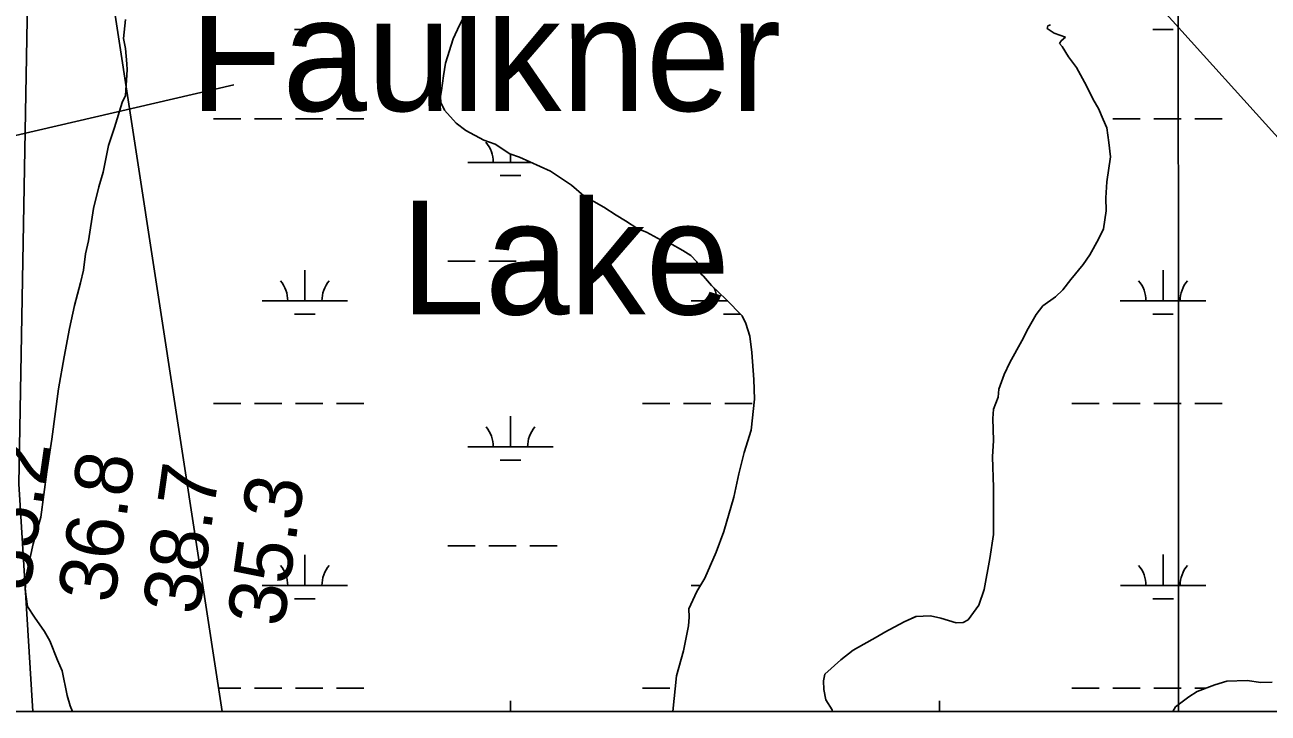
# Model space of a CAD drawing. Extents: x 3263578 to 3301413, y 764927 to 798602.
# Drawn here: x 3295210 to 3296664, y 775829 to 776634 of the extents above; entities that cross this region are included whole.
import ezdxf

# ---------------------------------------------------------------- set-up
doc = ezdxf.new("R2010")
doc.units = 0
for name, color, linetype in [('V-GRID-FRAM', 7, 'Continuous'), ('V-GRID-MAJR', 7, 'Continuous'), ('V-RIVR-IDEN', 7, 'Continuous'), ('V-RIVR-RANG', 7, 'Continuous'), ('V-SITE-VEGE', 7, 'Continuous'), ('V-TOPO-MINR', 7, 'Continuous'), ('V-WETL-SWMP', 7, 'Continuous')]:
    doc.layers.add(name, color=color, linetype=linetype)

msp = doc.modelspace()

# ---------------------------------------------------------------- linework, layer by layer
at = {"layer": 'V-GRID-FRAM'}
msp.add_lwpolyline([(3267734.9, 794015.5), (3299171.2, 794017.8), (3299180.4, 775831.7), (3267728.3, 775829.4), (3267734.9, 794015.5)], dxfattribs=at)
at = {"layer": 'V-GRID-MAJR'}
msp.add_spline([(3296559.4, 775831.5), (3296556.8, 781892.5), (3296554.1, 787954.5), (3296551.5, 794016.6), (3296551.5, 794017.6)], degree=3, dxfattribs=at)
at = {"layer": 'V-RIVR-RANG'}
msp.add_line((3295454.3, 776563.8), (3294246.5, 776283), dxfattribs=at)
at = {"layer": 'V-SITE-VEGE'}
for p, q in [((3295727.8, 776651.9), (3295718.5, 776633.6)), ((3295325.4, 776618.1), (3295327.7, 776640.1)), ((3295718.5, 776633.6), (3295711, 776617.4)), ((3296405.8, 776629.7), (3296406.6, 776632.7)), ((3296413.9, 776624), (3296405.8, 776629.7)), ((3296406.6, 776632.7), (3296409.6, 776633.8)), ((3295327.8, 776606.2), (3295325.4, 776618.1)), ((3295711, 776617.4), (3295702, 776589.2)), ((3296427, 776619.5), (3296413.9, 776624)), ((3296420.3, 776612.2), (3296422.2, 776615.3)), ((3296422.2, 776615.3), (3296427, 776619.5)), ((3295329.4, 776588.3), (3295327.8, 776606.2)), ((3296423.4, 776608.4), (3296420.3, 776612.2)), ((3296430.8, 776596.6), (3296423.4, 776608.4)), ((3295329.6, 776581.3), (3295329.4, 776588.3)), ((3295702, 776589.2), (3295699.5, 776574.1)), ((3296440.2, 776584), (3296430.8, 776596.6)), ((3295327.6, 776551.3), (3295329.6, 776581.3)), ((3295699.5, 776574.1), (3295697.1, 776557.1)), ((3296451.9, 776562.4), (3296440.2, 776584)), ((3295697.1, 776557.1), (3295696.3, 776550.1)), ((3296459.4, 776546.7), (3296451.9, 776562.4)), ((3295314.9, 776514), (3295323.9, 776543.2)), ((3295323.9, 776543.2), (3295327.6, 776551.3)), ((3295696.3, 776550.1), (3295696.6, 776543.1)), ((3295696.6, 776543.1), (3295700.9, 776534.3)), ((3296465.7, 776536), (3296459.4, 776546.7)), ((3295700.9, 776534.3), (3295714.4, 776518.8)), ((3296471.2, 776523.2), (3296465.7, 776536)), ((3295307.7, 776492.8), (3295314.9, 776514)), ((3295714.4, 776518.8), (3295725.6, 776510.2)), ((3296475.5, 776513.4), (3296471.2, 776523.2)), ((3296478, 776496.5), (3296475.5, 776513.4)), ((3295725.6, 776510.2), (3295746.9, 776498.9)), ((3295746.9, 776498.9), (3295760, 776494.4)), ((3295301.7, 776461.7), (3295307.7, 776492.8)), ((3295760, 776494.4), (3295777.4, 776483)), ((3296479.6, 776479.6), (3296478, 776496.5)), ((3295777.4, 776483), (3295788.5, 776479.4)), ((3295788.5, 776479.4), (3295824.9, 776462.7)), ((3296475.6, 776450.5), (3296479.6, 776479.6)), ((3295296.3, 776444.6), (3295301.7, 776461.7)), ((3295824.9, 776462.7), (3295849.4, 776446.5)), ((3295290.2, 776419.4), (3295296.3, 776444.6)), ((3295849.4, 776446.5), (3295863.8, 776434)), ((3296474.2, 776431.5), (3296475.6, 776450.5)), ((3295863.8, 776434), (3295887.2, 776420.9)), ((3296474.7, 776416.6), (3296474.2, 776431.5)), ((3295284.5, 776381.3), (3295290.2, 776419.4)), ((3295887.2, 776420.9), (3295901.5, 776411.4)), ((3295901.5, 776411.4), (3295912.6, 776404.8)), ((3296471.4, 776395.6), (3296474.7, 776416.6)), ((3295912.6, 776404.8), (3295926.9, 776395.3)), ((3295926.9, 776395.3), (3295937, 776391.6)), ((3295937, 776391.6), (3295954.3, 776382.2)), ((3295954.3, 776382.2), (3295964.4, 776378.6)), ((3296455.5, 776365.1), (3296465.9, 776383.4)), ((3296465.9, 776383.4), (3296471.4, 776395.6)), ((3295281, 776366.3), (3295284.5, 776381.3)), ((3295964.4, 776378.6), (3295979.6, 776370.1)), ((3295979.6, 776370.1), (3295988.8, 776364.4)), ((3295278.6, 776347.2), (3295281, 776366.3)), ((3295988.8, 776364.4), (3295996, 776356.7)), ((3295996, 776356.7), (3295997.1, 776353.7)), ((3295997.1, 776353.7), (3295996.2, 776350.7)), ((3296433.5, 776336.4), (3296447.9, 776353.9)), ((3296447.9, 776353.9), (3296455.5, 776365.1)), ((3295275.1, 776332.2), (3295278.6, 776347.2)), ((3295996.2, 776350.7), (3295999.4, 776345.8)), ((3295999.4, 776345.8), (3296000.5, 776342.9)), ((3296000.5, 776342.9), (3296003.6, 776340)), ((3296003.6, 776340), (3296012.9, 776329.3)), ((3295268, 776306), (3295275.1, 776332.2)), ((3296012.9, 776329.3), (3296030.4, 776313)), ((3296415.3, 776315.9), (3296424, 776324.1)), ((3296424, 776324.1), (3296433.5, 776336.4)), ((3296030.4, 776313), (3296049, 776293.6)), ((3296400.7, 776305.4), (3296415.3, 776315.9)), ((3295262, 776278.9), (3295268, 776306)), ((3296383.6, 776278.9), (3296393, 776295.2)), ((3296393, 776295.2), (3296400.7, 776305.4)), ((3296049, 776293.6), (3296053.3, 776284.8)), ((3296053.3, 776284.8), (3296057.8, 776270)), ((3295256.1, 776245.8), (3295262, 776278.9)), ((3296057.8, 776270), (3296060.4, 776251.1)), ((3296376.1, 776264.7), (3296383.6, 776278.9)), ((3296060.4, 776251.1), (3296062.5, 776219.3)), ((3296362, 776239.3), (3296376.1, 776264.7)), ((3295249.4, 776208.6), (3295256.1, 776245.8)), ((3296355.5, 776225.1), (3296362, 776239.3)), ((3296349.1, 776207.9), (3296355.5, 776225.1)), ((3295241.4, 776149.5), (3295249.4, 776208.6)), ((3296062.5, 776219.3), (3296063.2, 776196.4)), ((3296348.4, 776198.9), (3296349.1, 776207.9)), ((3296063.2, 776196.4), (3296059.5, 776160.3)), ((3296342.9, 776184.8), (3296348.4, 776198.9)), ((3296342.2, 776173.8), (3296342.9, 776184.8)), ((3296343.1, 776147.9), (3296342.2, 776173.8)), ((3295235.7, 776111.4), (3295241.4, 776149.5)), ((3296059.5, 776160.3), (3296051.4, 776134.2)), ((3296341.7, 776128.9), (3296343.1, 776147.9)), ((3296051.4, 776134.2), (3296045.2, 776109)), ((3296342.9, 776093.1), (3296341.7, 776128.9)), ((3295228.5, 776058.3), (3295235.7, 776111.4)), ((3296045.2, 776109), (3296039.1, 776081.9)), ((3296342.8, 776038.2), (3296342.9, 776093.1)), ((3296039.1, 776081.9), (3296027.5, 776041.6)), ((3295219.5, 776027.1), (3295228.5, 776058.3)), ((3296027.5, 776041.6), (3296018.4, 776017.4)), ((3296338.7, 776010.1), (3296342.8, 776038.2)), ((3295211.7, 775992), (3295219.5, 776027.1)), ((3296018.4, 776017.4), (3296005.4, 775987)), ((3296332, 775974), (3296338.7, 776010.1)), ((3295210.4, 775974), (3295211.7, 775992)), ((3296005.4, 775987), (3295996, 775971.7)), ((3295213, 775954.1), (3295210.4, 775974)), ((3295996, 775971.7), (3295986.7, 775951.5)), ((3296325.6, 775955.8), (3296332, 775974)), ((3295221.4, 775941.4), (3295213, 775954.1)), ((3295986.7, 775951.5), (3295987, 775941.5)), ((3296313.2, 775938.5), (3296325.6, 775955.8)), ((3295232.9, 775924.9), (3295221.4, 775941.4)), ((3295986.3, 775931.5), (3295980.3, 775902.4)), ((3295987, 775941.5), (3295986.3, 775931.5)), ((3296216, 775924.2), (3296238.5, 775936)), ((3296238.5, 775936), (3296252.3, 775942.4)), ((3296252.3, 775942.4), (3296269.2, 775943)), ((3296269.2, 775943), (3296281.2, 775940.4)), ((3296281.2, 775940.4), (3296299.4, 775935)), ((3296299.4, 775935), (3296307.3, 775935.3)), ((3296307.3, 775935.3), (3296313.2, 775938.5)), ((3295239.3, 775914.1), (3295232.9, 775924.9)), ((3296178.8, 775903.1), (3296207.2, 775919)), ((3296207.2, 775919), (3296216, 775924.2)), ((3295248, 775891.4), (3295239.3, 775914.1)), ((3295980.3, 775902.4), (3295972.3, 775873.2)), ((3296164.2, 775891.6), (3296178.8, 775903.1)), ((3295253.4, 775878.7), (3295248, 775891.4)), ((3296145.8, 775875), (3296164.2, 775891.6)), ((3295259.4, 775849.9), (3295253.4, 775878.7)), ((3295972.3, 775873.2), (3295967.7, 775831.5)), ((3296144.1, 775867), (3296145.8, 775875)), ((3296144.4, 775857), (3296144.1, 775867)), ((3296602, 775862.4), (3296581.3, 775854.7)), ((3296615.8, 775866.8), (3296602, 775862.4)), ((3296639.7, 775867.6), (3296615.8, 775866.8)), ((3296655.8, 775865.2), (3296639.7, 775867.6)), ((3296668.7, 775865.6), (3296655.8, 775865.2)), ((3295262.8, 775838.1), (3295259.4, 775849.9)), ((3296146.8, 775845.1), (3296144.4, 775857)), ((3296154.2, 775833.4), (3296146.8, 775845.1)), ((3296571.5, 775848.4), (3296556, 775836.9)), ((3296581.3, 775854.7), (3296571.5, 775848.4)), ((3295265.6, 775831.4), (3295262.8, 775838.1)), ((3295967.7, 775831.5), (3295265.6, 775831.4)), ((3296154.7, 775831.5), (3296154.2, 775833.4)), ((3296552.5, 775831.5), (3296154.7, 775831.5)), ((3296556, 775836.9), (3296552.5, 775831.5))]:
    msp.add_line(p, q, dxfattribs=at)
at = {"layer": 'V-TOPO-MINR'}
msp.add_lwpolyline([(3295219.4, 775831.4), (3295202.8, 776097.4), (3295218.5, 776965.5), (3295106.3, 777286.8), (3294931, 777730.3), (3294625.5, 778522.3), (3294144, 779432.3), (3293914.9, 780038.8), (3293875.1, 780405.1), (3293866.3, 780527.2), (3293880.6, 780798.5), (3293922, 781083.2), (3293958.4, 781200.7)], dxfattribs=at)
at = {"layer": 'V-WETL-SWMP'}
for p, q in [((3297279.6, 775831.6), (3296128.1, 777109.7)), ((3295312.6, 776665.8), (3295440.7, 775831.5)), ((3295718.5, 776633.6), (3295727.8, 776651.9)), ((3295711, 776617.4), (3295718.5, 776633.6)), ((3296406.6, 776632.7), (3296405.7, 776629.7)), ((3296405.7, 776629.7), (3296413.9, 776624)), ((3296409.6, 776633.8), (3296406.6, 776632.7)), ((3295525.4, 776628.5), (3295549.4, 776628.5)), ((3295702, 776589.2), (3295711, 776617.4)), ((3296413.9, 776624), (3296427, 776619.5)), ((3296422.2, 776615.3), (3296420.3, 776612.2)), ((3296427, 776619.5), (3296422.2, 776615.3)), ((3296529.2, 776628.6), (3296553.2, 776628.6)), ((3296420.3, 776612.2), (3296423.4, 776608.4)), ((3296423.4, 776608.4), (3296430.8, 776596.6)), ((3295699.5, 776574.1), (3295702, 776589.2)), ((3296430.8, 776596.6), (3296440.2, 776584)), ((3295697.1, 776557.1), (3295699.5, 776574.1)), ((3296440.2, 776584), (3296451.9, 776562.4)), ((3295696.3, 776550.1), (3295697.1, 776557.1)), ((3296451.9, 776562.4), (3296459.4, 776546.7)), ((3295696.6, 776543.1), (3295696.3, 776550.1)), ((3295700.9, 776534.3), (3295696.6, 776543.1)), ((3296459.4, 776546.7), (3296465.7, 776536)), ((3295714.3, 776518.8), (3295700.9, 776534.3)), ((3296465.7, 776536), (3296471.1, 776523.2)), ((3295430.6, 776523.9), (3295462.6, 776523.9)), ((3295478.6, 776523.9), (3295510.6, 776523.9)), ((3295526.6, 776523.9), (3295558.6, 776523.9)), ((3295574.6, 776523.9), (3295606.6, 776523.9)), ((3295725.6, 776510.2), (3295714.3, 776518.8)), ((3296471.1, 776523.2), (3296475.5, 776513.4)), ((3296475.5, 776513.4), (3296478, 776496.5)), ((3296482.4, 776523.9), (3296514.4, 776523.9)), ((3296530.4, 776523.9), (3296562.4, 776523.9)), ((3296578.4, 776523.9), (3296610.4, 776523.9)), ((3295746.9, 776498.9), (3295725.6, 776510.2)), ((3295760, 776494.4), (3295746.9, 776498.9)), ((3295777.4, 776483), (3295760, 776494.4)), ((3296478, 776496.5), (3296479.6, 776479.6)), ((3295727.9, 776473.1), (3295802.1, 776473.1)), ((3295788.5, 776479.4), (3295777.4, 776483)), ((3295777.9, 776473.1), (3295777.9, 776482.8)), ((3295824.9, 776462.7), (3295788.5, 776479.4)), ((3296479.6, 776479.6), (3296475.6, 776450.5)), ((3295765.9, 776457.7), (3295789.9, 776457.7)), ((3295849.4, 776446.5), (3295824.9, 776462.7)), ((3295863.8, 776434), (3295849.4, 776446.5)), ((3296475.6, 776450.5), (3296474.2, 776431.5)), ((3295887.2, 776420.9), (3295863.8, 776434)), ((3296474.2, 776431.5), (3296474.7, 776416.6)), ((3295901.4, 776411.4), (3295887.2, 776420.9)), ((3295912.6, 776404.8), (3295901.4, 776411.4)), ((3296474.7, 776416.6), (3296471.4, 776395.6)), ((3295926.9, 776395.3), (3295912.6, 776404.8)), ((3295937, 776391.6), (3295926.9, 776395.3)), ((3295954.3, 776382.2), (3295937, 776391.6)), ((3295964.4, 776378.6), (3295954.3, 776382.2)), ((3296465.9, 776383.4), (3296455.5, 776365.1)), ((3296471.4, 776395.6), (3296465.9, 776383.4)), ((3295979.6, 776370.1), (3295964.4, 776378.6)), ((3295988.8, 776364.4), (3295979.6, 776370.1)), ((3295704.5, 776357.7), (3295736.5, 776357.7)), ((3295752.5, 776357.7), (3295784.5, 776357.7)), ((3295800.5, 776357.7), (3295832.5, 776357.7)), ((3295996, 776356.7), (3295988.8, 776364.4)), ((3295997.1, 776353.7), (3295996, 776356.7)), ((3295996.2, 776350.7), (3295997.1, 776353.7)), ((3296447.9, 776353.9), (3296433.5, 776336.4)), ((3296455.5, 776365.1), (3296447.9, 776353.9)), ((3295537.4, 776311.3), (3295537.4, 776347.3)), ((3295999.4, 776345.8), (3295996.2, 776350.7)), ((3296000.5, 776342.9), (3295999.4, 776345.8)), ((3296003.6, 776340), (3296000.5, 776342.9)), ((3296012.9, 776329.3), (3296003.6, 776340)), ((3296541.2, 776311.3), (3296541.2, 776347.3)), ((3296030.4, 776313), (3296012.9, 776329.3)), ((3296424, 776324.1), (3296415.3, 776315.9)), ((3296433.5, 776336.4), (3296424, 776324.1)), ((3295487.4, 776311.3), (3295587.4, 776311.3)), ((3295989.3, 776311.3), (3296032, 776311.3)), ((3296049, 776293.6), (3296030.4, 776313)), ((3296415.3, 776315.9), (3296400.6, 776305.4)), ((3296491.2, 776311.3), (3296591.2, 776311.3)), ((3295525.4, 776295.8), (3295549.4, 776295.8)), ((3296027.3, 776295.9), (3296046.9, 776295.9)), ((3296393, 776295.2), (3296383.6, 776278.9)), ((3296400.6, 776305.4), (3296393, 776295.2)), ((3296529.2, 776295.9), (3296553.2, 776295.9)), ((3296053.3, 776284.8), (3296049, 776293.6)), ((3296057.8, 776270), (3296053.3, 776284.8)), ((3296060.4, 776251.1), (3296057.8, 776270)), ((3296383.6, 776278.9), (3296376.1, 776264.7)), ((3296062.5, 776219.3), (3296060.4, 776251.1)), ((3296376.1, 776264.7), (3296362, 776239.3)), ((3296362, 776239.3), (3296355.5, 776225.1)), ((3296355.5, 776225.1), (3296349.1, 776207.9)), ((3296063.2, 776196.4), (3296062.5, 776219.3)), ((3296349.1, 776207.9), (3296348.4, 776198.9)), ((3296059.4, 776160.3), (3296063.2, 776196.4)), ((3296348.4, 776198.9), (3296342.9, 776184.8)), ((3295430.6, 776191.2), (3295462.6, 776191.2)), ((3295478.6, 776191.2), (3295510.6, 776191.2)), ((3295526.6, 776191.2), (3295558.6, 776191.2)), ((3295574.6, 776191.2), (3295606.6, 776191.2)), ((3295932.5, 776191.2), (3295964.5, 776191.2)), ((3295980.5, 776191.2), (3296012.5, 776191.2)), ((3296028.5, 776191.2), (3296060.5, 776191.2)), ((3296342.9, 776184.8), (3296342.2, 776173.8)), ((3296434.4, 776191.3), (3296466.4, 776191.3)), ((3296482.4, 776191.3), (3296514.4, 776191.3)), ((3296530.4, 776191.3), (3296562.4, 776191.3)), ((3296578.4, 776191.3), (3296610.4, 776191.3)), ((3295777.9, 776140.5), (3295777.9, 776176.5)), ((3296342.2, 776173.8), (3296343.1, 776147.9)), ((3296051.3, 776134.1), (3296059.4, 776160.3)), ((3295727.9, 776140.5), (3295827.9, 776140.5)), ((3296343.1, 776147.9), (3296341.7, 776128.9)), ((3295765.9, 776125), (3295789.9, 776125)), ((3296045.2, 776109), (3296051.3, 776134.1)), ((3296341.7, 776128.9), (3296342.9, 776093.1)), ((3296039.1, 776081.9), (3296045.2, 776109)), ((3296342.9, 776093.1), (3296342.8, 776038.2)), ((3296027.5, 776041.6), (3296039.1, 776081.9)), ((3296018.4, 776017.4), (3296027.5, 776041.6)), ((3296342.8, 776038.2), (3296338.7, 776010.1)), ((3295704.5, 776025), (3295736.5, 776025)), ((3295752.5, 776025), (3295784.5, 776025)), ((3295800.5, 776025), (3295832.5, 776025)), ((3295537.5, 775978.6), (3295537.5, 776014.6)), ((3296005.4, 775987), (3296018.4, 776017.4)), ((3296338.7, 776010.1), (3296332, 775974)), ((3296541.3, 775978.7), (3296541.3, 776014.7)), ((3295487.5, 775978.6), (3295587.5, 775978.6)), ((3295989.4, 775978.6), (3296000.2, 775978.6)), ((3295996, 775971.7), (3296005.4, 775987)), ((3296491.3, 775978.7), (3296591.3, 775978.7)), ((3295525.5, 775963.2), (3295549.5, 775963.2)), ((3295986.7, 775951.5), (3295996, 775971.7)), ((3296332, 775974), (3296325.6, 775955.8)), ((3296529.3, 775963.2), (3296553.3, 775963.2)), ((3295987, 775941.5), (3295986.7, 775951.5)), ((3296325.6, 775955.8), (3296313.2, 775938.5)), ((3295980.3, 775902.4), (3295986.3, 775931.5)), ((3295986.3, 775931.5), (3295987, 775941.5)), ((3296238.5, 775936), (3296216, 775924.2)), ((3296252.2, 775942.4), (3296238.5, 775936)), ((3296269.2, 775943), (3296252.2, 775942.4)), ((3296281.2, 775940.4), (3296269.2, 775943)), ((3296299.4, 775935), (3296281.2, 775940.4)), ((3296307.3, 775935.3), (3296299.4, 775935)), ((3296313.2, 775938.5), (3296307.3, 775935.3)), ((3296207.2, 775919), (3296178.8, 775903.1)), ((3296216, 775924.2), (3296207.2, 775919)), ((3295972.3, 775873.2), (3295980.3, 775902.4)), ((3296178.8, 775903.1), (3296164.2, 775891.6)), ((3296164.2, 775891.6), (3296145.8, 775875)), ((3295967.7, 775831.5), (3295972.3, 775873.2)), ((3296145.8, 775875), (3296144.1, 775867)), ((3295436.6, 775858.5), (3295462.6, 775858.5)), ((3295478.6, 775858.5), (3295510.6, 775858.5)), ((3295526.6, 775858.5), (3295558.6, 775858.5)), ((3295574.6, 775858.5), (3295606.6, 775858.5)), ((3295932.5, 775858.5), (3295964.5, 775858.5)), ((3296144.1, 775867), (3296144.4, 775857)), ((3296434.4, 775858.6), (3296466.4, 775858.6)), ((3296482.4, 775858.6), (3296514.4, 775858.6)), ((3296530.4, 775858.6), (3296562.4, 775858.6)), ((3296578.4, 775858.6), (3296591.8, 775858.6)), ((3296581.3, 775854.7), (3296602, 775862.4)), ((3296602, 775862.4), (3296615.8, 775866.8)), ((3296615.8, 775866.8), (3296639.7, 775867.6)), ((3296639.7, 775867.6), (3296655.7, 775865.2)), ((3296655.7, 775865.2), (3296668.7, 775865.6)), ((3296144.4, 775857), (3296146.8, 775845.1)), ((3296146.8, 775845.1), (3296154.2, 775833.4)), ((3296556, 775836.9), (3296571.5, 775848.4)), ((3296571.5, 775848.4), (3296581.3, 775854.7)), ((3295440.7, 775831.5), (3295967.7, 775831.5)), ((3295777.9, 775831.5), (3295777.9, 775843.8)), ((3296154.2, 775833.4), (3296154.7, 775831.5)), ((3296154.7, 775831.5), (3296552.5, 775831.5)), ((3296279.8, 775831.5), (3296279.8, 775843.8)), ((3296552.5, 775831.5), (3296556, 775836.9))]:
    msp.add_line(p, q, dxfattribs=at)
for centre, start, end in [((3295722.6, 776473.6), 359.2323, 40.776), ((3295833.1, 776473.6), 177.6826, 180.776), ((3295482.2, 776311.7), 359.2323, 40.776), ((3295592.7, 776311.7), 139.2323, 180.776), ((3295984.1, 776311.8), 359.2323, 24.1389), ((3296486, 776311.8), 359.2323, 40.776), ((3296596.5, 776311.8), 139.2323, 180.776), ((3295722.7, 776140.9), 359.2323, 40.776), ((3295833.2, 776140.9), 139.2323, 180.776), ((3295482.2, 775979.1), 359.2323, 40.776), ((3295592.7, 775979.1), 139.2323, 180.776), ((3295984.1, 775979.1), 39.0115, 40.776), ((3296486, 775979.1), 359.2323, 40.776), ((3296596.5, 775979.1), 139.2323, 180.776)]:
    msp.add_arc(centre, 35.2, start, end, dxfattribs=at)

# ---------------------------------------------------------------- texts
at = {"layer": 'V-RIVR-IDEN'}
for s, p in [('Faulkner', (3295402.5, 776533.2)), ('Lake', (3295649.2, 776295.4))]:
    msp.add_text(s, height=133, dxfattribs=at).set_placement(p)
at = {"layer": 'V-RIVR-RANG'}
for s, p in [('35.2', (3295215.4, 775970.5)), ('36.8', (3295314.4, 775956.7)), ('38.7', (3295413.5, 775942.8)), ('35.3', (3295512.5, 775929))]:
    msp.add_text(s, height=67, rotation=81.9183, dxfattribs=at).set_placement(p)

doc.saveas('drawing.dxf')
